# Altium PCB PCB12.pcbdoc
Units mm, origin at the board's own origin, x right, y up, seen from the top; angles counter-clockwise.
Board outline 82.04 x 43.43 mm, 2 copper layers (Top Layer, Bottom Layer); 25 components, 16 nets, 62 pads, 22 vias.
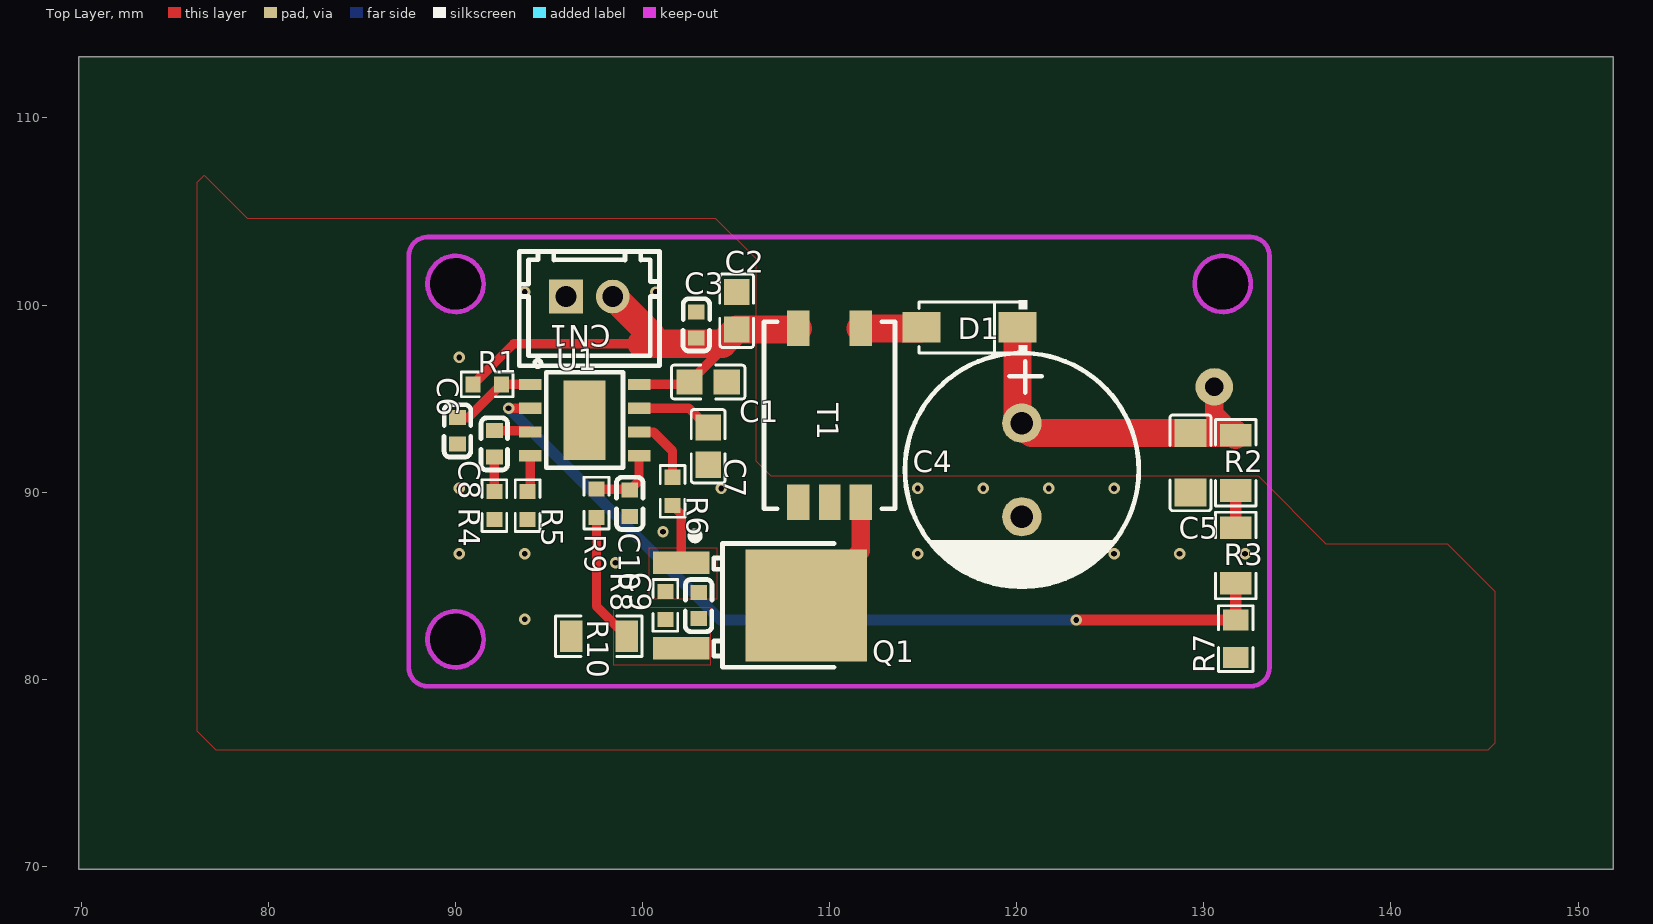
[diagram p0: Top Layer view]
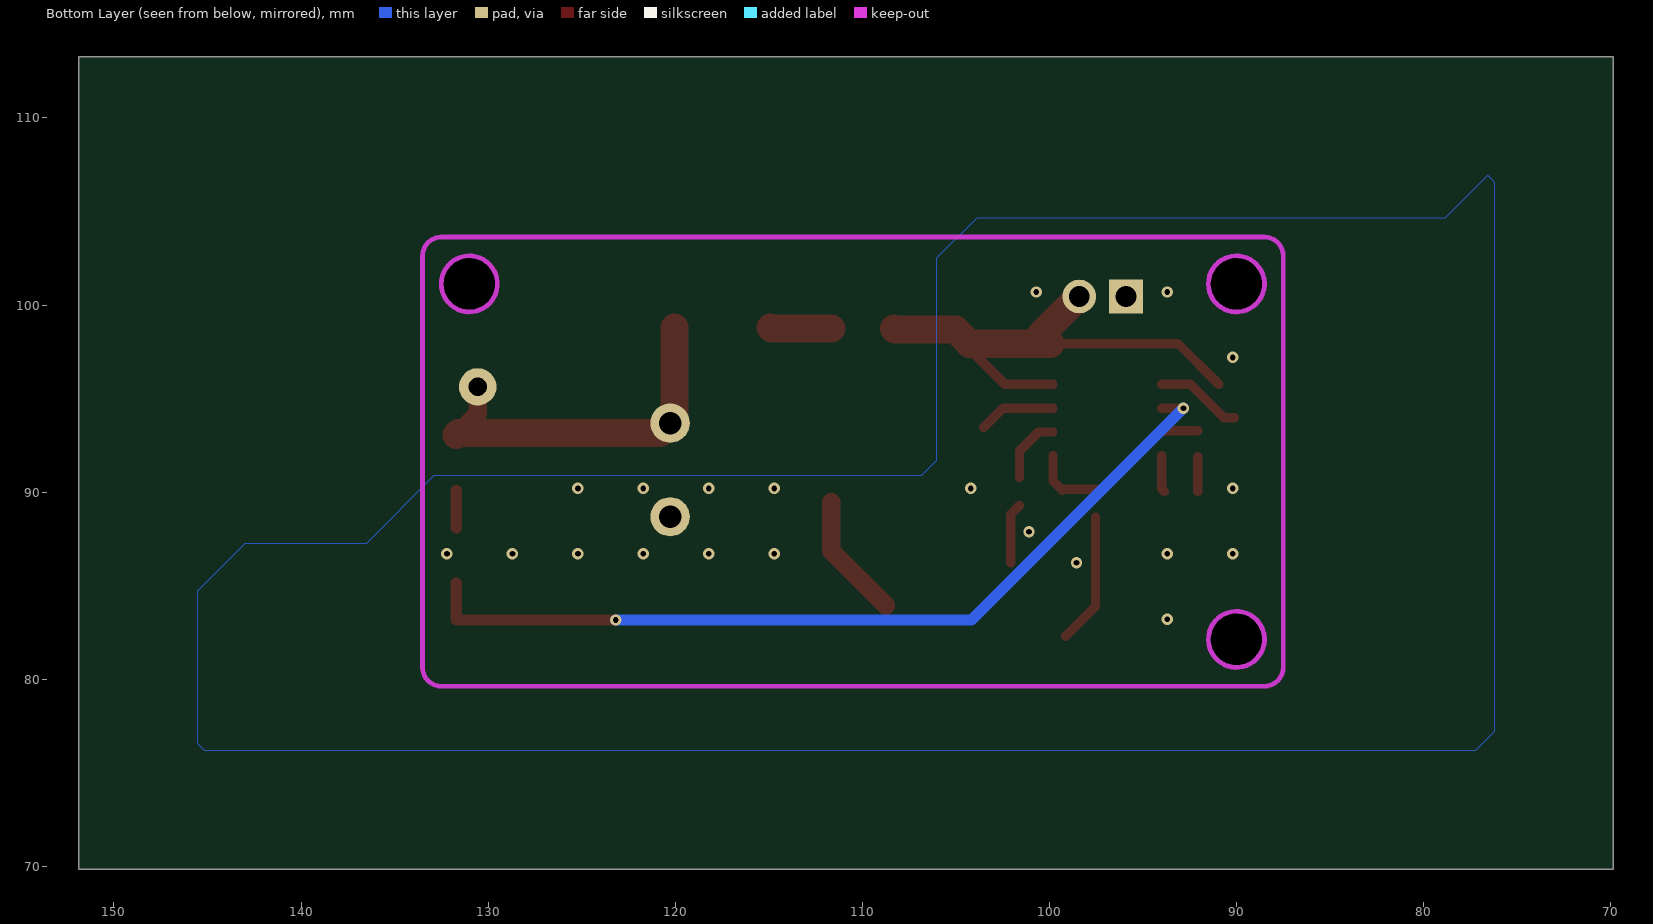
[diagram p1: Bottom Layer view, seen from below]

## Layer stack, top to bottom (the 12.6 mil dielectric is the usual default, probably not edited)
Top Layer: signal copper (thickness not stored)
Dielectric: dielectric 0.32, FR-4, Dk 4.8
Bottom Layer: signal copper (thickness not stored)

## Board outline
151.892,69.85 69.85,69.85 69.85,113.284 151.892,113.284
cut-out: 91.503,101.132 ccw(c90.003,101.132) 88.503,101.132 ccw(c90.003,101.132)
cut-out: 91.503,82.132 ccw(c90.003,82.132) 88.503,82.132 ccw(c90.003,82.132)
cut-out: 132.503,101.132 ccw(c131.003,101.132) 129.503,101.132 ccw(c131.003,101.132)

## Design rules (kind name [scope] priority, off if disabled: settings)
Clearance copperThickness1oz [All] p1: gap=0.178 ignorepadtopadclearanceinfootprint=FALSE except(0.102: Track-Track; 0.152: Track-SMDPad SMDPad-SMDPad Track-THPad SMDPad-THPad THPad-THPad Track-Via SMDPad-Via THPad-Via Via-Via Track-Fill SMDPad-Fill THPad-Fill Via-Fill Fill-Fill SMDPad-Region THPad-Region Via-Region Fill-Region Region-Region Track-Poly SMDPad-Poly THPad-Poly Via-Poly Fill-Poly Poly-Poly Track-Text SMDPad-Text THPad-Text Via-Text Fill-Text Region-Text Poly-Text Text-Text Track-Hole SMDPad-Hole THPad-Hole Via-Hole Fill-Hole Region-Hole Poly-Hole Text-Hole; 0.3: Track-Region Region-Poly Track-Sheet SMDPad-Sheet THPad-Sheet Via-Sheet Fill-Sheet Region-Sheet Poly-Sheet Text-Sheet Sheet-Hole)
Clearance copperThickness2oz [All] p1: gap=0.178 ignorepadtopadclearanceinfootprint=FALSE except(0.152: Track-SMDPad SMDPad-SMDPad Track-THPad SMDPad-THPad THPad-THPad Track-Via SMDPad-Via THPad-Via Via-Via Track-Fill SMDPad-Fill THPad-Fill Via-Fill Fill-Fill SMDPad-Region THPad-Region Via-Region Fill-Region Region-Region Track-Poly SMDPad-Poly THPad-Poly Via-Poly Fill-Poly Poly-Poly Track-Text SMDPad-Text THPad-Text Via-Text Fill-Text Region-Text Poly-Text Text-Text Track-Hole SMDPad-Hole THPad-Hole Via-Hole Fill-Hole Region-Hole Poly-Hole Text-Hole; 0.203: Track-Track; 0.3: Track-Region Region-Poly Track-Sheet SMDPad-Sheet THPad-Sheet Via-Sheet Fill-Sheet Region-Sheet Poly-Sheet Text-Sheet Sheet-Hole)
DiffPairsRouting differentialPair [All] p1: maxuncoupledlength=10 maxlimit=5.9843 mostfreqgap=5.9843 toplayer_minwidth=5 toplayer_prefwidth=10 toplayer_maxwidth=100 bottomlayer_minwidth=5 bottomlayer_prefwidth=10 bottomlayer_maxwidth=100
PasteMaskExpansion pasteMaskExpansion [All] p1:
PlaneConnect innerPlane [All] p1: planeconnectstyle=Relief reliefexpansion=0.508 reliefentries=4 reliefconductorwidth=0.254 reliefairgap=0.254
PolygonConnect copperRegion [All] p1: connectstyle=Direct reliefentries=4 reliefconductorwidth=10 polygonreliefangle="90 Angle" airgapwidth=10
RoutingVias viaSize [All] p1: viastyle="Through Hole" holewidth=12.0078 minholewidth=11.811 maxholewidth=248.0314 width=24.0158 minwidth=19.685 maxwidth=393.7008
SolderMaskExpansion solderMaskExpansion [All] p1: useseparateexpansions=TRUE expansion=2.0079 expansionbottom=2.0079
Width copperThickness1oz [All] p1: maxlimit=100 minlimit=5 preferedwidth=10
Width copperThickness2oz [All] p1: maxlimit=100 minlimit=8 preferedwidth=10

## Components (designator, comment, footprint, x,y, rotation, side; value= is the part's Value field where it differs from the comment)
C1 "0805X106K250NT" C0805 103.505,95.885 r180 top
C2 "0805X106K250NT" C0805 105.029,99.695 r270 top
C3 "0603B104K500NT" C0603 102.87,98.933 r270 top
C4 "EGS2EM470W16OT" CAP-TH_BD12.5-P5.00-D0.6-FD 120.269,91.186 r270 top
C5 "1206B104K251NT_C2909525" C1206 129.286,91.567 r90 top
C6 "0603B104K500NT" C0603 90.105,93.283 r90 top
C7 "0805X106K250NT" C0805 103.505,92.456 r270 top
C8 "0603B103K500NT" C0603 92.075,92.583 r90 top
C9 "CC0603KRX7R9BB102" C0603 102.997,83.947 r90 top
C10 "0603B104K500NT" C0603 99.314,89.408 r90 top
CN1 "ZX-XH2.54-2PZZ" CONN-TH_2P-P2.50_HX25003-2A 97.155,100.457 r0 top
D1 "ES1J_C412438" SMA_L4.4-W2.8-LS5.4-RD 117.475,98.806 r180 top
Q1 "NCEP02515K" TO-252-3_L6.6-W6.1-P4.58-LS10.1-BR-2 105.41,83.947 r180 top
R1 "0603WAF1002T5E" R0603 91.694,95.758 r180 top
R2 "1206W4F1003T5E" R1206 131.699,91.567 r270 top
R3 "1206W4F1003T5E" R1206 131.699,86.614 r270 top
R4 "0603WAF1002T5E" R0603 92.075,89.281 r90 top
R5 "0603WAF1003T5E" R0603 93.853,89.281 r90 top
R6 "0603WAF100JT5E" R0603 101.6,90.043 r270 top
R7 "0805W8F1501T5E" R0805 131.699,82.169 r90 top
R8 "0603WAF1002T5E" R0603 101.219,83.947 r90 top
R9 "0603WAF200JT5E" R0603 97.536,89.408 r270 top
R10 "1206W4F100LT5E" R1206 97.663,82.296 r0 top
T1 "TTRN-060S-013-T" TTRN-060S-013 109.982,94.107 r0 top
U1 "ASP3756" ESOP-8_L4.9-W3.9-P1.27-LS6.0-BL-EP4.2 96.901,93.853 r270 top

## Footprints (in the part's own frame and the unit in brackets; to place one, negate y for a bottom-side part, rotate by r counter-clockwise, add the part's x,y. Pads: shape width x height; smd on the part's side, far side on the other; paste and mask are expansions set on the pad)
C0603 [mm]
  rect 0.8x0.9 smd: 1(-0.7,0) 2(0.7,0)
  silkscreen extent -1.41,-0.71 1.39,0.72
C0805 [mm]
  rect 1.41x1.35 smd: 1(-1,0) 2(1,0)
  silkscreen extent -1.96,-0.9 1.96,0.9
C1206 [mm]
  rect 1.485x1.728 smd: 1(-1.593,0) 2(1.593,0)
  silkscreen extent -2.56,-1.09 2.56,1.09
CAP-TH_BD12.5-P5.00-D0.6-FD [mm]
  round 2.1 hole 1.2: 1(-2.5,0) 2(2.5,0)
  silkscreen extent -6.25,-6.25 6.25,6.25
CONN-TH_2P-P2.50_HX25003-2A [mm]
  rect 1.8x1.8 hole 1.1: 1(-1.25,0)
  round 1.8 hole 1.1: 2(1.25,0)
  silkscreen extent -3.75,-3.7 3.75,2.41
ESOP-8_L4.9-W3.9-P1.27-LS6.0-BL-EP4.2 [mm]
  rect 0.6x1.2 smd: 1(-1.905,-2.908) 2(-0.635,-2.908) 3(0.635,-2.908) 4(1.905,-2.908) 5(1.905,2.908) 6(0.635,2.908) 7(-0.635,2.908) 8(-1.905,2.908)
  rect 4.25x2.25 smd: 9(0,0)
  silkscreen extent -3.2,-2.67 2.55,2.05
R0603 [mm]
  rect 0.806x0.864 smd: 1(-0.753,0) 2(0.753,0)
  silkscreen extent -1.39,-0.66 1.39,0.66
R0805 [mm]
  rect 1.133x1.377 smd: 1(-1,0) 2(1,0)
  silkscreen extent -1.76,-0.92 1.76,0.92
R1206 [mm]
  rect 1.208x1.701 smd: 1(-1.479,0) 2(1.479,0)
  silkscreen extent -2.31,-1.08 2.31,1.08
SMA_L4.4-W2.8-LS5.4-RD [mm]
  rect 2.046x1.62 smd: 1(-2.565,0) 2(2.565,0)
  silkscreen extent -3.08,-1.44 2.7,1.44
TO-252-3_L6.6-W6.1-P4.58-LS10.1-BR-2 [mm]
  rect 3x1.2 smd: 1(3.342,-2.285) 3(3.342,2.285)
  rect 6.5x6 smd: 2(-3.343,0)
  silkscreen extent -4.83,-3.92 2.81,3.3
TTRN-060S-013 [mm]
  rect 1.2x1.9 smd: 1(-1.675,4.65) 2(1.675,4.651) 3(-1.675,-4.65) 5(1.675,-4.651)
  rect 1.15x1.9 smd: EMPTY(0.025,-4.65)
  silkscreen extent -3.5,-5 3.5,5

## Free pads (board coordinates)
  round 2 hole 1: 1(130.556,95.631)

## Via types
v1: diameter 0.61, hole 0.304, Top Layer to Bottom Layer, 20 vias
v2: diameter 0.61, hole 0.305, Top Layer to Bottom Layer, 2 vias

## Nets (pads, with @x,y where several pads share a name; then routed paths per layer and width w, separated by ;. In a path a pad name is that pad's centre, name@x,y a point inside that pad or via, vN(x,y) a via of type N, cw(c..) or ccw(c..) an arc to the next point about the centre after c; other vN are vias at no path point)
$1N1088: C6.2 R1.1 U1.1 | length 4.6
  Top Layer w0.5: C6.2 90.672,93.983 R1.1 U1.1
$1N1091: C8.2 U1.3 | length 1.9
  Top Layer w0.5: C8.2 93.928,93.283 U1.3
$1N1092: C8.1 R4.2 | length 1.8
  Top Layer w0.5: R4.2 C8.1
$1N1093: R5.2 U1.4 | length 2
  Top Layer w0.5: R5.2 93.993,90.174 U1.4
$1N1095: C7.1 U1.7 | length 4.1
  Top Layer w0.5: U1.7 102.473,94.488 C7.1
$1N1102: C10.2 R9.1 U1.5 | length 3.8
  Top Layer w0.5: R9.1 99.261,90.161 C10.2 99.809,90.603 U1.5
$1N1104: R6.1 U1.6 | length 3.6
  Top Layer w0.5: U1.6 100.584,93.218 101.6,92.202 R6.1
$1N1105: C9.2 Q1.1 R6.2 R8.2 | length 3.3
  Top Layer w0.5: R6.2 102.068,88.822 Q1.1
$1N1106: R2.2 R3.1 | length 2
  Top Layer w0.6: R3.1 R2.2
$1N1108: C9.1 Q1.3 R8.1 R9.2 R10.2 | length 7
  Top Layer w0.5: R9.2 97.536,83.902 R10.2
$1N2253: D1.2 T1.2 | length 3.3
  Top Layer w1.5: T1.2 114.861,98.758 D1.2
$1N2342: Q1.2 T1.5 | length 6.7
  Top Layer w1: Q1.2 111.657,86.852 T1.5
FB: 
GND: C1.1 C2.1 C3.1 C4.2 C5.1 C6.1 C7.2 C10.1 CN1.1 R4.1 R5.1 R7.1 R10.1 T1.3 U1.9
  other v1: 93.7,83.2 98.552,86.233 90.2,86.7 93.7,86.7 114.7,86.7 118.2,86.7 121.7,86.7 125.2,86.7 128.7,86.7 132.2,86.7 101.092,87.884 90.2,90.2 104.2,90.2 114.7,90.2 118.2,90.2 121.7,90.2 125.2,90.2 90.2,97.2 93.7,100.7 100.7,100.7
HV: C4.1 C5.2 D1.1 pad.1 R2.1 | length 19.8
  Top Layer w1: pad.1 130.556,94.189 R2.1@131.585,93.16
  Top Layer w1.5: D1.1 120.04,93.915 C4.1 120.795,93.16 C5.2 131.585,93.16 R2.1
VIN: C1.2 C2.2 C3.2 CN1.2 R1.2 T1.1 U1.8 | length 27.7
  Top Layer w0.5: R1.2 93.116,97.933 99.953,97.933 ; U1.8 102.378,95.758 C1.2 104.267,97.647 104.267,97.933
  Top Layer w1.5: CN1.2 100.441,98.421 99.953,97.933 104.267,97.933 C2.2 108.245,98.695 T1.1
pads on no net: R3.2 R7.2 T1.EMPTY U1.2
copper on no net: | length 46.7
  Top Layer w0.5: v2(92.837,94.488) 93.993,94.488
  Top Layer w0.6: v2(123.174,83.169) 131.699,83.169 131.699,85.135
  Bottom Layer w0.6: v2(92.837,94.488) 104.156,83.169 v2(123.174,83.169)

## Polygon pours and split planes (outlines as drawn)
$1N1108 on Top Layer (solid, remove dead copper): 98.425,80.772 103.632,80.772 103.632,83.82 98.425,83.82
$1N1105 on Top Layer (solid, remove dead copper, pour order 2): 100.33,84.293 103.997,84.293 103.997,86.995 100.33,86.995
GND on Top Layer (solid, remove dead copper, pour order 4): 106.045,91.666 106.842,90.869 132.905,90.869 136.525,87.249 143.002,87.249 145.542,84.709 145.542,76.581 145.161,76.2 77.216,76.2 76.2,77.216 76.2,106.553 76.581,106.934 78.867,104.648 103.886,104.648 106.045,102.489
GND on Bottom Layer (solid, remove dead copper, pour order 12): 106.045,91.666 106.842,90.869 132.905,90.869 136.525,87.249 143.002,87.249 145.542,84.709 145.542,76.581 145.161,76.2 77.216,76.2 76.2,77.216 76.2,106.553 76.581,106.934 78.867,104.648 103.886,104.648 106.045,102.489

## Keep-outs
Board Outline Layer:
  lines w0.254: 87.503,80.632 ccw(c88.503,80.632) 88.503,79.632 132.503,79.632 ccw(c132.503,80.632) 133.503,80.632 133.503,102.632 ccw(c132.503,102.632) 132.503,103.632 88.503,103.632 ccw(c88.503,102.632) 87.503,102.632 87.503,80.632
Multi-Layer:
  circle w0.254: c90.003,101.132 r1.5
  circle w0.254: c90.003,82.132 r1.5
  circle w0.254: c131.003,101.132 r1.5

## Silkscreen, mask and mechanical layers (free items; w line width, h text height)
Mechanical Layer:
  circle w0.025: c90.003,101.132 r1.5
  circle w0.025: c90.003,82.132 r1.5
  circle w0.025: c131.003,101.132 r1.5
